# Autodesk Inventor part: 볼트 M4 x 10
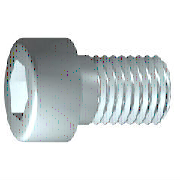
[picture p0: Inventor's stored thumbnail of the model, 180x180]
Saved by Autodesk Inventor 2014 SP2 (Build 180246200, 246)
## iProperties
IsCustomPart: 0
Created: 2012-02
Part Number: 볼트 M4 x 10
Material: 스테인리스강
Description: 6각 소켓 머리 캡 나사
Document SubType Name: Modeling
Standard: ISO 4762
Designer: mduedu
Standard Revision: Fourth edition 2004-03-01
Standards Organization: ISO
Language: ko-KR
Size Designation: M4 x 10
Categories: <MemberInstance><Categories><Category DisplayName="조임쇠" InternalName="e4da775c-781d-43d5-af7c-5136215cf5a6" Mnemonic="FSTN"><Category DisplayName="볼트" InternalN
Density: 8.08 g/cm^3
Appearance: 반광택
Author: mduedu
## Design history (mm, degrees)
sketch "스케치1"
  geometry: L1 (-1, 0)-(10, 0); L2 (10, 0)-(10, 2); L3 (10, 2)-(1.75, 2); L4 (1.75, 2)-(1.32, 2); L5 (1.32, 2)-(0, 2); L6 (0, 2)-(0, 3.5); L7 (0, 3.5)-(-4, 3.5); L8 (-4, 3.5)-(-4, 1.732); L9 (-4, 1.732)-(-2, 1.732); L10 (-2, 1.732)-(-1, 0); L11 (-6.8, 0)-(12.8, 0) reference; L12 (0, -0.7)-(0, 4.2) reference; L13 (1.75, 2)-(0, 2)
  constraints: 22 end point, 6 parallel, 2 collinear, 2 perpendicular, 1 horizontal, 1 point on line
  dimensions: "d1" = 8.25 distance from line of L3.end L2 (= GEL); "d2" = 0.42952 distance of L4.end L3.end (computed from GAL); "d3" = 4 distance between parallel lines of L8 L6 (= KOH); "d4" = 2 distance of L8.end L9.end (= INTI); "d5" = 60 deg angle of L10 L1; "d6" = 4 diameter of L3 L1 (= GD); "d7" = 4 diameter of L5 L1 (= BDM); "d8" = 3.4641 diameter of L9 L1 (= 1.1547 x SW); "d9" = 7 diameter of L7 L1 (= KOD); "d26" = 10 distance between parallel lines of L12 L2 (= NLG)
revolve "본체" sketch "스케치1" stored, may be unused: angle "d10" = 90 deg
sketch "스케치2"
  geometry: L1 (0, -4.9)-(0, 4.9) reference; L2 (-4.9, 0)-(4.9, 0) reference; L3 (1.732, 0)-(0.866, -1.5); L4 (0.866, -1.5)-(-0.866, -1.5); L5 (-0.866, -1.5)-(-1.732, 0); L6 (-1.732, 0)-(-0.866, 1.5); L7 (-0.866, 1.5)-(0.866, 1.5); L8 (0.866, 1.5)-(1.732, 0); 2 further points
  constraints: 12 end point, 1 coincident, 1 horizontal alignment, 1 point on line, 12 other
extrude "슬롯" join sketch "스케치2" stored distance "d11" = 10; taper "d12" = 0 deg
workplane "Work Plane1"
fillet "Fillet2" dims "d30" = 0.1 (= R)
body "Solid1"
fillet "모깎기1" dims "d17" = 0.4 (= RR)
feature "스레드" dims "d13" = 8.25 (= GEL), "d14" = 0
chamfer "모따기1" distance "d15" = 0.42941 (= -0.5 x SPD + 0.5 x GD); stored, may be unused: second distance "d16" = 0.42941 (= GUL), angle "d27" = 45 deg
other parameters: "GD" = 4 [user parameter; used in 2 equation terms], "NLG" = 10 [user parameter; used in 1 equation term], "GEL" = 8.25 [user parameter; used in 2 equation terms], "KOD" = 7 [user parameter; used in 1 equation term], "KOH" = 4 [user parameter; used in 1 equation term], "INTI" = 2 [user parameter; used in 1 equation term], "GAL" = 0.42941 (= 0.61345 x PTC) [user parameter; used in 1 equation term], "GUL" = 0.42941 (= 0.61345 x PTC) [user parameter; used in 1 equation term], "BDM" = 4 (= NND) [user parameter; used in 1 equation term], "SW" = 3 [user parameter; used in 2 equation terms], "RR" = 0.4 [user parameter; used in 1 equation term], "SPD" = 3.14117 (= NND - 1.2269 x PTC) [user parameter; used in 1 equation term], "d19" = 0, "d28" = 0, "d29" = 0, "R" = 0.1 [user parameter; used in 1 equation term], "TOA" = 30 deg [user parameter], "GD1" = 3.14117 (= THREADDIA - 1.2269 x PTC) [user parameter], "THREADDIA" = 4 [user parameter; used in 1 equation term], "FAWI" = 45 deg [user parameter], "TPU" = 14.28571 (computed from PTC) [user parameter], "PTC" = 0.7 [user parameter; used in 5 equation terms], "NND" = 4 [user parameter; used in 2 equation terms], "E0" = 3.465 (= 1.155 x SW) [user parameter]
